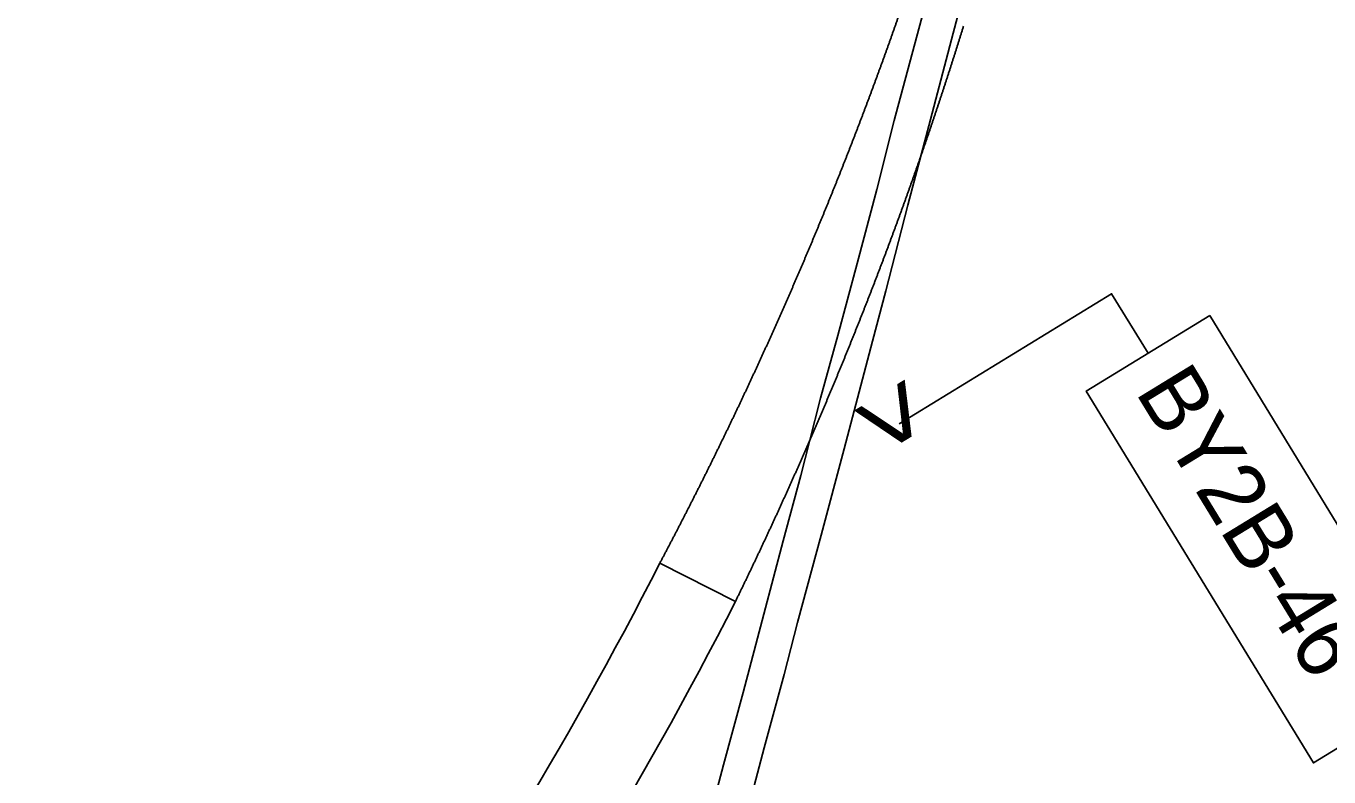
# Model space of a CAD drawing. Extents: x 1771071 to 1790027, y 804210 to 823391.
# Drawn here: x 1782402 to 1783163, y 814593 to 815031 of the extents above; entities that cross this region are included whole.
import ezdxf

# ---------------------------------------------------------------- set-up
doc = ezdxf.new("R2010")
doc.units = 0
for name, color, linetype in [('Default', 7, 'Continuous'), ('Exist Roads EOP', 7, 'Continuous'), ('Old_Level_57', 7, 'Continuous'), ('Proposed Right of Way Monument PSD Text', 7, 'Continuous'), ('Scratch_Level_8', 7, 'Continuous')]:
    doc.layers.add(name, color=color, linetype=linetype)

msp = doc.modelspace()

# ---------------------------------------------------------------- linework, layer by layer
at = {"layer": 'Default'}
msp.add_lwpolyline([(1782912.39, 814798.66), (1783036.54, 814874.62), (1783057.8, 814839.9)], dxfattribs=at)
msp.add_lwpolyline([(1783093.86, 814861.93), (1783226.52, 814644.81), (1783154.4, 814600.75), (1783021.74, 814817.87)], close=True, dxfattribs=at)
at = {"layer": 'Exist Roads EOP'}
for points in [[(1782810.5, 814522.45), (1782819.71, 814557.13), (1782833.63, 814609.67), (1782845.19, 814652.34), (1782853.11, 814682.7), (1782866.83, 814733.67), (1782880.33, 814784.04), (1782896.83, 814847.05), (1782904.69, 814876.34), (1782917.48, 814926.43), (1782930.77, 814976.43), (1782943.98, 815026.78), (1782949.05, 815045.92), (1782955.94, 815070.93), (1782968.77, 815118.62), (1782976.32, 815145.42), (1782981.66, 815163.9), (1782994.39, 815213.76), (1783001.18, 815239.78), (1783009.61, 815271.62)], [(1782798.27, 814556.34), (1782809.82, 814599.63), (1782821.24, 814641.98), (1782833.33, 814687.58), (1782844.77, 814730.36), (1782855.02, 814768.66), (1782860.01, 814788.32), (1782866.57, 814813.78), (1782876.56, 814850.36), (1782887.82, 814892.28), (1782899.33, 814935.44), (1782909.53, 814975.79), (1782921.25, 815019.23), (1782932.71, 815062.01), (1782944.15, 815104.21), (1782955.09, 815145.17), (1782966.82, 815189.08), (1782971.17, 815207.42), (1782981.42, 815245.29), (1782983.08, 815250.42)]]:
    msp.add_lwpolyline(points, dxfattribs=at)
for points in [[(1782454.8, 814433.05), (1782425.79, 814455.52), (1782395.47, 814479.87), (1782368.44, 814502.06), (1782336.7, 814528.74), (1782306.5, 814555), (1782272.52, 814585.37), (1782237.96, 814617.26), (1782203.42, 814650.14), (1782169.77, 814683.38), (1782135.62, 814718.19), (1782114.92, 814739.97), (1782090.36, 814766.45), (1782056.11, 814804.23), (1782024.57, 814840.15), (1781996.1, 814874.23), (1781962.65, 814915.16), (1781930.52, 814956.23), (1781901.27, 814994.73), (1781879.88, 815023.5), (1781865.55, 815043.2)], [(1782447.39, 814411.49), (1782417.41, 814434.76), (1782388.46, 814457.81), (1782364.95, 814476.92), (1782332.84, 814503.63), (1782317.89, 814516.39), (1782288.73, 814541.74), (1782259.15, 814568.04), (1782231.71, 814593.59), (1782203.19, 814620.46), (1782173.93, 814648.95), (1782145.34, 814677.22), (1782115.25, 814707.98), (1782082.01, 814743.51), (1782053.72, 814774.62), (1782020.97, 814811.58), (1781993.17, 814843.95), (1781966.57, 814876.13), (1781940.26, 814908.56), (1781913.84, 814942.34), (1781892.83, 814970.15), (1781866.04, 815005.9), (1781848.36, 815030.23)], [(1781123.7, 814794.56), (1781151.95, 814749.7), (1781175.35, 814711.94), (1781204.02, 814667.22), (1781230.05, 814626.42), (1781255.51, 814585.11), (1781282.93, 814541.39), (1781309.04, 814500.81), (1781338.07, 814453.82), (1781362.44, 814415.66), (1781389.1, 814373.22), (1781417.2, 814328.4), (1781443.82, 814286), (1781469.22, 814245.27), (1781496.33, 814201.88), (1781523.28, 814159.28), (1781551.49, 814114.9), (1781575, 814076.8), (1781602.27, 814034.47), (1781628.68, 813992.42), (1781657.71, 813946.44), (1781682.97, 813906.24), (1781710.54, 813862.11), (1781734.73, 813823.58), (1781763.09, 813779.24), (1781788.41, 813738.38), (1781814.81, 813696.35), (1781842.37, 813653.36), (1781868.91, 813610.68), (1781895.83, 813568.71), (1781924.39, 813523.58), (1781950.61, 813481.8), (1781976.68, 813442.67), (1782004.37, 813401.37), (1782031.99, 813360.12), (1782060.77, 813317.53), (1782089.19, 813276.64), (1782119.2, 813233.31), (1782146.2, 813195.67), (1782175.13, 813155.14), (1782204.07, 813115.4), (1782233.24, 813075.72), (1782263.79, 813034.43), (1782294.03, 812994.29), (1782325.04, 812953.86), (1782354.41, 812916.21), (1782385, 812877.38), (1782417.21, 812837.26), (1782449.43, 812797.65), (1782479.54, 812761.76), (1782513.17, 812720.66), (1782543.05, 812684.98), (1782576.35, 812645.89), (1782608.48, 812608.74), (1782640.69, 812571.37), (1782677.39, 812530.96), (1782710.34, 812494.65), (1782741.2, 812460.83), (1782775.54, 812424.09), (1782810.15, 812387.02), (1782844.36, 812350.73), (1782880.69, 812313.19), (1782914.85, 812277.64), (1782949.87, 812242.16), (1782985.13, 812206.92), (1783022.44, 812170.42), (1783054.86, 812138.57), (1783094.75, 812100.54), (1783130.02, 812066.91), (1783162.74, 812036.24), (1783200.85, 812001.49), (1783239.6, 811965.96), (1783275.52, 811933.35), (1783312.46, 811900.79)]]:
    msp.add_spline(points, degree=3, dxfattribs=at)
at = {"layer": 'Scratch_Level_8'}
for p, q in [((1782772.67, 814717.43), (1782816.77, 814694.95)), ((1782816.77, 814694.95), (1782772.67, 814717.43)), ((1782816.77, 814694.95), (1782772.67, 814717.43))]:
    msp.add_line(p, q, dxfattribs=at)
for centre, radius, start, end in [((1784215.15, 816723.25), 2878, 220.79704, 234.02645), ((1784215.15, 816723.25), 2922, 220.79704, 233.96949), ((1780718.84, 815764.32), 2305.25, 324.09033, 332.9908), ((1780718.84, 815764.32), 2354.75, 324.08963, 332.9908)]:
    msp.add_arc(centre, radius, start, end, dxfattribs=at)
for points in [[(1782889.9, 814975.91), (1782890.24, 814976.81), (1782890.58, 814977.71), (1782890.92, 814978.6), (1782891.26, 814979.5), (1782891.6, 814980.4), (1782891.94, 814981.3), (1782892.28, 814982.2), (1782892.62, 814983.09), (1782892.96, 814983.99), (1782893.3, 814984.89), (1782893.64, 814985.79), (1782893.98, 814986.69), (1782894.31, 814987.59), (1782894.65, 814988.49), (1782894.99, 814989.39), (1782895.32, 814990.28), (1782895.66, 814991.18), (1782895.99, 814992.08), (1782896.33, 814992.98), (1782896.66, 814993.88), (1782897, 814994.78), (1782897.33, 814995.68), (1782897.67, 814996.59), (1782898, 814997.49), (1782898.33, 814998.39), (1782898.67, 814999.29), (1782899, 815000.19), (1782899.33, 815001.09), (1782899.66, 815001.99), (1782899.99, 815002.89), (1782900.32, 815003.79), (1782900.65, 815004.7), (1782900.98, 815005.6), (1782901.31, 815006.5), (1782901.64, 815007.4), (1782901.97, 815008.3), (1782902.3, 815009.21), (1782902.63, 815010.11), (1782902.96, 815011.01), (1782903.28, 815011.92), (1782903.61, 815012.82), (1782903.94, 815013.72), (1782904.26, 815014.62), (1782904.59, 815015.53), (1782904.91, 815016.43), (1782905.24, 815017.34), (1782905.56, 815018.24), (1782905.89, 815019.14), (1782906.21, 815020.05), (1782906.54, 815020.95), (1782906.86, 815021.86), (1782907.18, 815022.76), (1782907.51, 815023.67), (1782907.83, 815024.57), (1782908.15, 815025.48), (1782908.47, 815026.38), (1782908.79, 815027.29), (1782909.11, 815028.19), (1782909.43, 815029.1), (1782909.75, 815030), (1782910.07, 815030.91), (1782910.39, 815031.82), (1782910.71, 815032.72), (1782911.03, 815033.63), (1782911.35, 815034.53), (1782911.66, 815035.44), (1782911.98, 815036.35), (1782912.3, 815037.25), (1782912.61, 815038.16), (1782912.93, 815039.07), (1782913.25, 815039.98), (1782913.56, 815040.88), (1782913.88, 815041.79), (1782914.19, 815042.7)], [(1782950.03, 815030.92), (1782949.74, 815029.99), (1782949.45, 815029.06), (1782949.16, 815028.12), (1782948.87, 815027.19), (1782948.58, 815026.26), (1782948.29, 815025.33), (1782948, 815024.4), (1782947.7, 815023.46), (1782947.41, 815022.53), (1782947.12, 815021.6), (1782946.82, 815020.67), (1782946.53, 815019.74), (1782946.24, 815018.81), (1782945.94, 815017.88), (1782945.65, 815016.95), (1782945.35, 815016.02), (1782945.06, 815015.08), (1782944.76, 815014.15), (1782944.46, 815013.22), (1782944.17, 815012.29), (1782943.87, 815011.36), (1782943.57, 815010.43), (1782943.28, 815009.5), (1782942.98, 815008.57), (1782942.68, 815007.64), (1782942.38, 815006.71), (1782942.08, 815005.78), (1782941.78, 815004.85), (1782941.48, 815003.93), (1782941.18, 815003), (1782940.88, 815002.07), (1782940.58, 815001.14), (1782940.28, 815000.21), (1782939.97, 814999.28), (1782939.67, 814998.35), (1782939.37, 814997.42), (1782939.06, 814996.5), (1782938.76, 814995.57), (1782938.46, 814994.64), (1782938.15, 814993.71), (1782937.85, 814992.78), (1782937.54, 814991.86), (1782937.24, 814990.93), (1782936.93, 814990), (1782936.62, 814989.07), (1782936.32, 814988.15), (1782936.01, 814987.22), (1782935.7, 814986.29), (1782935.39, 814985.37), (1782935.09, 814984.44), (1782934.78, 814983.51), (1782934.47, 814982.59), (1782934.16, 814981.66), (1782933.85, 814980.73), (1782933.54, 814979.81), (1782933.23, 814978.88), (1782932.92, 814977.96), (1782932.6, 814977.03), (1782932.29, 814976.1), (1782931.98, 814975.18), (1782931.67, 814974.25), (1782931.35, 814973.33), (1782931.04, 814972.4), (1782930.73, 814971.48), (1782930.41, 814970.55), (1782930.1, 814969.63), (1782929.78, 814968.7), (1782929.47, 814967.78), (1782929.15, 814966.85), (1782928.84, 814965.93), (1782928.52, 814965.01), (1782928.2, 814964.08), (1782927.89, 814963.16), (1782927.57, 814962.24)], [(1782863.57, 814909.94), (1782863.94, 814910.82), (1782864.31, 814911.71), (1782864.68, 814912.59), (1782865.05, 814913.48), (1782865.41, 814914.37), (1782865.78, 814915.25), (1782866.15, 814916.14), (1782866.52, 814917.03), (1782866.88, 814917.91), (1782867.25, 814918.8), (1782867.61, 814919.69), (1782867.98, 814920.58), (1782868.34, 814921.46), (1782868.71, 814922.35), (1782869.07, 814923.24), (1782869.43, 814924.13), (1782869.8, 814925.02), (1782870.16, 814925.91), (1782870.52, 814926.79), (1782870.89, 814927.68), (1782871.25, 814928.57), (1782871.61, 814929.46), (1782871.97, 814930.35), (1782872.33, 814931.24), (1782872.69, 814932.13), (1782873.05, 814933.02), (1782873.41, 814933.91), (1782873.77, 814934.8), (1782874.13, 814935.69), (1782874.49, 814936.58), (1782874.85, 814937.47), (1782875.2, 814938.36), (1782875.56, 814939.25), (1782875.92, 814940.14), (1782876.27, 814941.04), (1782876.63, 814941.93), (1782876.99, 814942.82), (1782877.34, 814943.71), (1782877.7, 814944.6), (1782878.05, 814945.49), (1782878.41, 814946.39), (1782878.76, 814947.28), (1782879.11, 814948.17), (1782879.47, 814949.06), (1782879.82, 814949.96), (1782880.17, 814950.85), (1782880.53, 814951.74), (1782880.88, 814952.64), (1782881.23, 814953.53), (1782881.58, 814954.42), (1782881.93, 814955.32), (1782882.28, 814956.21), (1782882.63, 814957.1), (1782882.98, 814958), (1782883.33, 814958.89), (1782883.68, 814959.79), (1782884.03, 814960.68), (1782884.38, 814961.58), (1782884.72, 814962.47), (1782885.07, 814963.37), (1782885.42, 814964.26), (1782885.77, 814965.16), (1782886.11, 814966.05), (1782886.46, 814966.95), (1782886.8, 814967.84), (1782887.15, 814968.74), (1782887.49, 814969.63), (1782887.84, 814970.53), (1782888.18, 814971.43), (1782888.53, 814972.32), (1782888.87, 814973.22), (1782889.21, 814974.12), (1782889.55, 814975.01), (1782889.9, 814975.91)], [(1782927.57, 814962.23), (1782927.25, 814961.31), (1782926.93, 814960.39), (1782926.61, 814959.46), (1782926.29, 814958.54), (1782925.97, 814957.62), (1782925.65, 814956.69), (1782925.33, 814955.77), (1782925.01, 814954.85), (1782924.69, 814953.93), (1782924.37, 814953), (1782924.05, 814952.08), (1782923.73, 814951.16), (1782923.4, 814950.24), (1782923.08, 814949.31), (1782922.76, 814948.39), (1782922.43, 814947.47), (1782922.11, 814946.55), (1782921.78, 814945.63), (1782921.46, 814944.71), (1782921.13, 814943.79), (1782920.81, 814942.86), (1782920.48, 814941.94), (1782920.16, 814941.02), (1782919.83, 814940.1), (1782919.5, 814939.18), (1782919.17, 814938.26), (1782918.85, 814937.34), (1782918.52, 814936.42), (1782918.19, 814935.5), (1782917.86, 814934.58), (1782917.53, 814933.66), (1782917.2, 814932.74), (1782916.87, 814931.82), (1782916.54, 814930.9), (1782916.21, 814929.98), (1782915.88, 814929.06), (1782915.54, 814928.14), (1782915.21, 814927.23), (1782914.88, 814926.31), (1782914.55, 814925.39), (1782914.21, 814924.47), (1782913.88, 814923.55), (1782913.54, 814922.63), (1782913.21, 814921.72), (1782912.87, 814920.8), (1782912.54, 814919.88), (1782912.2, 814918.96), (1782911.87, 814918.04), (1782911.53, 814917.13), (1782911.19, 814916.21), (1782910.86, 814915.29), (1782910.52, 814914.38), (1782910.18, 814913.46), (1782909.84, 814912.54), (1782909.5, 814911.62), (1782909.16, 814910.71), (1782908.82, 814909.79), (1782908.48, 814908.88), (1782908.14, 814907.96), (1782907.8, 814907.04), (1782907.46, 814906.13), (1782907.12, 814905.21), (1782906.78, 814904.3), (1782906.44, 814903.38), (1782906.09, 814902.47), (1782905.75, 814901.55), (1782905.41, 814900.64), (1782905.06, 814899.72), (1782904.72, 814898.81), (1782904.38, 814897.89), (1782904.03, 814896.98), (1782903.69, 814896.06), (1782903.34, 814895.15), (1782902.99, 814894.24)], [(1782835.24, 814844.83), (1782835.64, 814845.71), (1782836.04, 814846.58), (1782836.43, 814847.45), (1782836.83, 814848.33), (1782837.22, 814849.2), (1782837.61, 814850.08), (1782838.01, 814850.95), (1782838.4, 814851.83), (1782838.8, 814852.7), (1782839.19, 814853.58), (1782839.58, 814854.45), (1782839.97, 814855.33), (1782840.36, 814856.2), (1782840.76, 814857.08), (1782841.15, 814857.96), (1782841.54, 814858.83), (1782841.93, 814859.71), (1782842.32, 814860.59), (1782842.71, 814861.46), (1782843.1, 814862.34), (1782843.49, 814863.22), (1782843.87, 814864.09), (1782844.26, 814864.97), (1782844.65, 814865.85), (1782845.04, 814866.73), (1782845.42, 814867.6), (1782845.81, 814868.48), (1782846.2, 814869.36), (1782846.58, 814870.24), (1782846.97, 814871.12), (1782847.35, 814872), (1782847.74, 814872.87), (1782848.12, 814873.75), (1782848.51, 814874.63), (1782848.89, 814875.51), (1782849.27, 814876.39), (1782849.66, 814877.27), (1782850.04, 814878.15), (1782850.42, 814879.03), (1782850.8, 814879.91), (1782851.19, 814880.79), (1782851.57, 814881.67), (1782851.95, 814882.55), (1782852.33, 814883.43), (1782852.71, 814884.32), (1782853.09, 814885.2), (1782853.47, 814886.08), (1782853.85, 814886.96), (1782854.22, 814887.84), (1782854.6, 814888.72), (1782854.98, 814889.6), (1782855.36, 814890.49), (1782855.74, 814891.37), (1782856.11, 814892.25), (1782856.49, 814893.13), (1782856.86, 814894.02), (1782857.24, 814894.9), (1782857.62, 814895.78), (1782857.99, 814896.67), (1782858.37, 814897.55), (1782858.74, 814898.43), (1782859.11, 814899.32), (1782859.49, 814900.2), (1782859.86, 814901.09), (1782860.23, 814901.97), (1782860.61, 814902.85), (1782860.98, 814903.74), (1782861.35, 814904.62), (1782861.72, 814905.51), (1782862.09, 814906.39), (1782862.46, 814907.28), (1782862.83, 814908.16), (1782863.2, 814909.05), (1782863.57, 814909.94)], [(1782902.99, 814894.23), (1782902.65, 814893.32), (1782902.3, 814892.41), (1782901.95, 814891.49), (1782901.6, 814890.58), (1782901.26, 814889.67), (1782900.91, 814888.75), (1782900.56, 814887.84), (1782900.21, 814886.93), (1782899.86, 814886.01), (1782899.51, 814885.1), (1782899.16, 814884.19), (1782898.81, 814883.28), (1782898.46, 814882.37), (1782898.11, 814881.45), (1782897.76, 814880.54), (1782897.4, 814879.63), (1782897.05, 814878.72), (1782896.7, 814877.81), (1782896.34, 814876.89), (1782895.99, 814875.98), (1782895.64, 814875.07), (1782895.28, 814874.16), (1782894.93, 814873.25), (1782894.57, 814872.34), (1782894.22, 814871.43), (1782893.86, 814870.52), (1782893.5, 814869.61), (1782893.15, 814868.7), (1782892.79, 814867.79), (1782892.43, 814866.88), (1782892.07, 814865.97), (1782891.72, 814865.06), (1782891.36, 814864.15), (1782891, 814863.24), (1782890.64, 814862.33), (1782890.28, 814861.42), (1782889.92, 814860.51), (1782889.56, 814859.61), (1782889.2, 814858.7), (1782888.84, 814857.79), (1782888.47, 814856.88), (1782888.11, 814855.97), (1782887.75, 814855.06), (1782887.39, 814854.16), (1782887.02, 814853.25), (1782886.66, 814852.34), (1782886.3, 814851.43), (1782885.93, 814850.53), (1782885.57, 814849.62), (1782885.2, 814848.71), (1782884.84, 814847.81), (1782884.47, 814846.9), (1782884.1, 814845.99), (1782883.74, 814845.09), (1782883.37, 814844.18), (1782883, 814843.27), (1782882.63, 814842.37), (1782882.27, 814841.46), (1782881.9, 814840.56), (1782881.53, 814839.65), (1782881.16, 814838.75), (1782880.79, 814837.84), (1782880.42, 814836.93), (1782880.05, 814836.03), (1782879.68, 814835.13), (1782879.31, 814834.22), (1782878.94, 814833.32), (1782878.56, 814832.41), (1782878.19, 814831.51), (1782877.82, 814830.6), (1782877.45, 814829.7), (1782877.07, 814828.8), (1782876.7, 814827.89), (1782876.32, 814826.99)], [(1782804.94, 814780.66), (1782805.36, 814781.53), (1782805.79, 814782.39), (1782806.21, 814783.25), (1782806.63, 814784.11), (1782807.05, 814784.97), (1782807.47, 814785.83), (1782807.89, 814786.69), (1782808.31, 814787.55), (1782808.73, 814788.42), (1782809.15, 814789.28), (1782809.57, 814790.14), (1782809.99, 814791), (1782810.41, 814791.87), (1782810.82, 814792.73), (1782811.24, 814793.59), (1782811.66, 814794.46), (1782812.08, 814795.32), (1782812.49, 814796.18), (1782812.91, 814797.05), (1782813.32, 814797.91), (1782813.74, 814798.78), (1782814.16, 814799.64), (1782814.57, 814800.51), (1782814.98, 814801.37), (1782815.4, 814802.24), (1782815.81, 814803.1), (1782816.22, 814803.97), (1782816.64, 814804.83), (1782817.05, 814805.7), (1782817.46, 814806.56), (1782817.87, 814807.43), (1782818.29, 814808.29), (1782818.7, 814809.16), (1782819.11, 814810.03), (1782819.52, 814810.89), (1782819.93, 814811.76), (1782820.34, 814812.63), (1782820.75, 814813.5), (1782821.16, 814814.36), (1782821.56, 814815.23), (1782821.97, 814816.1), (1782822.38, 814816.97), (1782822.79, 814817.83), (1782823.2, 814818.7), (1782823.6, 814819.57), (1782824.01, 814820.44), (1782824.42, 814821.31), (1782824.82, 814822.18), (1782825.23, 814823.05), (1782825.63, 814823.92), (1782826.04, 814824.79), (1782826.44, 814825.66), (1782826.84, 814826.53), (1782827.25, 814827.4), (1782827.65, 814828.27), (1782828.05, 814829.14), (1782828.46, 814830.01), (1782828.86, 814830.88), (1782829.26, 814831.75), (1782829.66, 814832.62), (1782830.06, 814833.49), (1782830.46, 814834.36), (1782830.86, 814835.23), (1782831.26, 814836.11), (1782831.66, 814836.98), (1782832.06, 814837.85), (1782832.46, 814838.72), (1782832.86, 814839.59), (1782833.26, 814840.47), (1782833.66, 814841.34), (1782834.05, 814842.21), (1782834.45, 814843.09), (1782834.85, 814843.96), (1782835.24, 814844.83)], [(1782876.32, 814826.99), (1782875.95, 814826.09), (1782875.57, 814825.18), (1782875.2, 814824.28), (1782874.82, 814823.38), (1782874.45, 814822.47), (1782874.07, 814821.57), (1782873.69, 814820.67), (1782873.32, 814819.77), (1782872.94, 814818.86), (1782872.56, 814817.96), (1782872.18, 814817.06), (1782871.8, 814816.16), (1782871.42, 814815.26), (1782871.04, 814814.36), (1782870.66, 814813.46), (1782870.28, 814812.55), (1782869.9, 814811.65), (1782869.52, 814810.75), (1782869.14, 814809.85), (1782868.76, 814808.95), (1782868.38, 814808.05), (1782867.99, 814807.15), (1782867.61, 814806.25), (1782867.23, 814805.35), (1782866.84, 814804.45), (1782866.46, 814803.55), (1782866.08, 814802.65), (1782865.69, 814801.75), (1782865.31, 814800.86), (1782864.92, 814799.96), (1782864.53, 814799.06), (1782864.15, 814798.16), (1782863.76, 814797.26), (1782863.37, 814796.36), (1782862.99, 814795.46), (1782862.6, 814794.57), (1782862.21, 814793.67), (1782861.82, 814792.77), (1782861.43, 814791.87), (1782861.04, 814790.98), (1782860.65, 814790.08), (1782860.26, 814789.18), (1782859.87, 814788.29), (1782859.48, 814787.39), (1782859.09, 814786.49), (1782858.7, 814785.6), (1782858.31, 814784.7), (1782857.92, 814783.8), (1782857.52, 814782.91), (1782857.13, 814782.01), (1782856.74, 814781.12), (1782856.34, 814780.22), (1782855.95, 814779.33), (1782855.55, 814778.43), (1782855.16, 814777.53), (1782854.76, 814776.64), (1782854.37, 814775.75), (1782853.97, 814774.85), (1782853.58, 814773.96), (1782853.18, 814773.06), (1782852.78, 814772.17), (1782852.38, 814771.27), (1782851.99, 814770.38), (1782851.59, 814769.49), (1782851.19, 814768.59), (1782850.79, 814767.7), (1782850.39, 814766.81), (1782849.99, 814765.91), (1782849.59, 814765.02), (1782849.19, 814764.13), (1782848.79, 814763.24), (1782848.39, 814762.34), (1782847.99, 814761.45), (1782847.58, 814760.56)], [(1782772.67, 814717.43), (1782773.59, 814719.18), (1782774.04, 814720.03), (1782774.49, 814720.88), (1782774.94, 814721.73), (1782775.38, 814722.57), (1782775.83, 814723.42), (1782776.27, 814724.27), (1782776.72, 814725.12), (1782777.17, 814725.97), (1782777.61, 814726.82), (1782778.06, 814727.66), (1782778.5, 814728.51), (1782778.94, 814729.36), (1782779.39, 814730.21), (1782779.83, 814731.06), (1782780.27, 814731.91), (1782780.72, 814732.76), (1782781.16, 814733.61), (1782781.6, 814734.46), (1782782.04, 814735.31), (1782782.48, 814736.16), (1782782.92, 814737.01), (1782783.36, 814737.87), (1782783.81, 814738.72), (1782784.24, 814739.57), (1782784.68, 814740.42), (1782785.12, 814741.27), (1782785.56, 814742.13), (1782786, 814742.98), (1782786.44, 814743.83), (1782786.88, 814744.68), (1782787.31, 814745.54), (1782787.75, 814746.39), (1782788.19, 814747.24), (1782788.62, 814748.1), (1782789.06, 814748.95), (1782789.5, 814749.8), (1782789.93, 814750.66), (1782790.37, 814751.51), (1782790.8, 814752.37), (1782791.23, 814753.22), (1782791.67, 814754.07), (1782792.1, 814754.93), (1782792.53, 814755.79), (1782792.97, 814756.64), (1782793.4, 814757.5), (1782793.83, 814758.35), (1782794.26, 814759.21), (1782794.7, 814760.06), (1782795.13, 814760.92), (1782795.56, 814761.78), (1782795.99, 814762.63), (1782796.42, 814763.49), (1782796.85, 814764.35), (1782797.28, 814765.2), (1782797.7, 814766.06), (1782798.13, 814766.92), (1782798.56, 814767.78), (1782798.99, 814768.63), (1782799.42, 814769.49), (1782799.84, 814770.35), (1782800.27, 814771.21), (1782800.7, 814772.07), (1782801.12, 814772.93), (1782801.55, 814773.79), (1782801.97, 814774.65), (1782802.4, 814775.5), (1782802.82, 814776.36), (1782803.25, 814777.22), (1782803.67, 814778.08), (1782804.1, 814778.94), (1782804.52, 814779.8), (1782804.94, 814780.67)], [(1782847.58, 814760.56), (1782847.18, 814759.67), (1782846.78, 814758.78), (1782846.38, 814757.89), (1782845.97, 814756.99), (1782845.57, 814756.1), (1782845.16, 814755.21), (1782844.76, 814754.32), (1782844.35, 814753.43), (1782843.95, 814752.54), (1782843.54, 814751.65), (1782843.14, 814750.76), (1782842.73, 814749.87), (1782842.32, 814748.98), (1782841.92, 814748.09), (1782841.51, 814747.2), (1782841.1, 814746.31), (1782840.69, 814745.42), (1782840.28, 814744.53), (1782839.87, 814743.64), (1782839.46, 814742.76), (1782839.05, 814741.87), (1782838.64, 814740.98), (1782838.23, 814740.09), (1782837.82, 814739.2), (1782837.41, 814738.31), (1782837, 814737.43), (1782836.59, 814736.54), (1782836.17, 814735.65), (1782835.76, 814734.76), (1782835.35, 814733.88), (1782834.93, 814732.99), (1782834.52, 814732.1), (1782834.11, 814731.22), (1782833.69, 814730.33), (1782833.28, 814729.44), (1782832.86, 814728.56), (1782832.44, 814727.67), (1782832.03, 814726.79), (1782831.61, 814725.9), (1782831.2, 814725.02), (1782830.78, 814724.13), (1782830.36, 814723.25), (1782829.94, 814722.36), (1782829.52, 814721.48), (1782829.1, 814720.59), (1782828.69, 814719.71), (1782828.27, 814718.82), (1782827.85, 814717.94), (1782827.43, 814717.06), (1782827, 814716.17), (1782826.58, 814715.29), (1782826.16, 814714.4), (1782825.74, 814713.52), (1782825.32, 814712.64), (1782824.9, 814711.76), (1782824.47, 814710.87), (1782824.05, 814709.99), (1782823.63, 814709.11), (1782823.2, 814708.23), (1782822.78, 814707.34), (1782822.35, 814706.46), (1782821.93, 814705.58), (1782821.5, 814704.7), (1782821.08, 814703.82), (1782820.65, 814702.94), (1782820.22, 814702.06), (1782819.8, 814701.17), (1782819.37, 814700.29), (1782818.94, 814699.41), (1782818.51, 814698.53), (1782818.09, 814697.65), (1782817.66, 814696.77), (1782816.77, 814694.95)]]:
    msp.add_spline(points, degree=3, dxfattribs=at)

# ---------------------------------------------------------------- texts
at = {"layer": 'Old_Level_57'}
msp.add_text('>', height=46.95, rotation=301.43915, dxfattribs=at).set_placement((1782880.12, 814806.45))
at = {"layer": 'Proposed Right of Way Monument PSD Text'}
msp.add_text('BY2B-46', height=37.325, rotation=301.42495, dxfattribs=at).set_placement((1783049.89, 814817.56))

doc.saveas('drawing.dxf')
